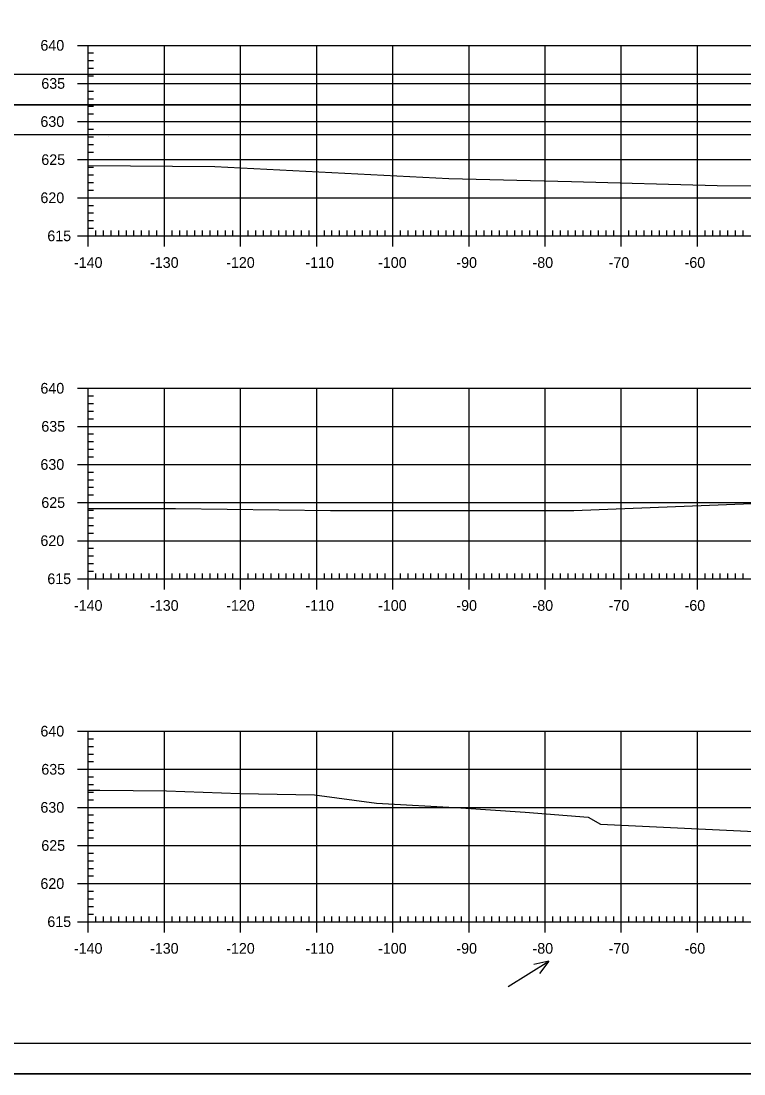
# Model space of a CAD drawing. Extents: x 1381471 to 1382703, y 370300 to 371487.
# Drawn here: x 1381987.8 to 1382082.7, y 370633.8 to 370772 of the extents above; entities that cross this region are included whole.
import ezdxf

# ---------------------------------------------------------------- set-up
doc = ezdxf.new("R2010")
doc.units = 0
for name, color, linetype in [('Level 26', 7, 'Continuous'), ('Level 40', 7, 'Continuous'), ('Level 45', 7, 'Continuous'), ('Level 6', 7, 'Continuous')]:
    doc.layers.add(name, color=color, linetype=linetype)

msp = doc.modelspace()

# ---------------------------------------------------------------- linework, layer by layer
at = {"layer": 'Level 26'}
msp.add_line((1381834.37, 370760.97), (1382167.7, 370760.97), dxfattribs=at)
msp.add_line((1381834.37, 370760.97), (1382167.7, 370760.97), dxfattribs=at)
for points in [[(1381834.36, 370974.3), (1382167.7, 370974.3), (1382167.7, 370760.97), (1381834.36, 370760.97)], [(1382080.69, 370970.41), (1382100.31, 370970.41), (1382100.31, 370960.53), (1382116.42, 370960.53), (1382139.62, 370960.53), (1382139.62, 370927.86), (1382162.83, 370927.86), (1382162.95, 370764.95), (1381846.77, 370764.95), (1381846.77, 370970.41)], [(1381834.36, 370760.97), (1382167.7, 370760.97), (1382167.7, 370547.63), (1381834.36, 370547.63)], [(1382080.69, 370757.07), (1382100.31, 370757.07), (1382100.31, 370747.19), (1382116.42, 370747.19), (1382139.62, 370747.19), (1382139.62, 370714.52), (1382162.83, 370714.52), (1382162.95, 370551.61), (1381846.77, 370551.61), (1381846.77, 370757.07)]]:
    msp.add_lwpolyline(points, close=True, dxfattribs=at)
at = {"layer": 'Level 40'}
for p, q in [((1382051.77, 370645.28), (1382057.11, 370648.58)), ((1382057.11, 370648.58), (1382055.11, 370648.16)), ((1382057.11, 370648.58), (1382055.85, 370646.97))]:
    msp.add_line(p, q, dxfattribs=at)
at = {"layer": 'Level 45'}
for p, q in [((1381995.21, 370768.78), (1381998.01, 370768.78)), ((1381996.61, 370768.78), (1382276.61, 370768.78)), ((1381996.61, 370743.78), (1381996.61, 370768.78)), ((1381996.61, 370743.78), (1381996.61, 370768.78)), ((1382006.61, 370743.78), (1382006.61, 370768.78)), ((1382016.61, 370743.78), (1382016.61, 370768.78)), ((1382026.61, 370743.78), (1382026.61, 370768.78)), ((1382036.61, 370743.78), (1382036.61, 370768.78)), ((1382046.61, 370743.78), (1382046.61, 370768.78)), ((1382056.61, 370743.78), (1382056.61, 370768.78)), ((1382066.61, 370743.78), (1382066.61, 370768.78)), ((1382076.61, 370743.78), (1382076.61, 370768.78)), ((1381996.61, 370767.78), (1381997.31, 370767.78)), ((1381996.61, 370766.78), (1381997.31, 370766.78)), ((1381996.61, 370765.78), (1381997.31, 370765.78)), ((1381996.61, 370764.78), (1381997.31, 370764.78)), ((1381995.21, 370763.78), (1381998.01, 370763.78)), ((1381996.61, 370763.78), (1382276.61, 370763.78)), ((1381996.61, 370762.78), (1381997.31, 370762.78)), ((1381996.61, 370761.78), (1381997.31, 370761.78)), ((1381996.61, 370760.78), (1381997.31, 370760.78)), ((1381995.21, 370758.78), (1381998.01, 370758.78)), ((1381996.61, 370759.78), (1381997.31, 370759.78)), ((1381996.61, 370758.78), (1382276.61, 370758.78)), ((1381996.61, 370757.78), (1381997.31, 370757.78)), ((1381996.61, 370756.78), (1381997.31, 370756.78)), ((1381996.61, 370755.78), (1381997.31, 370755.78)), ((1381996.61, 370754.78), (1381997.31, 370754.78)), ((1381995.21, 370753.78), (1381998.01, 370753.78)), ((1381996.61, 370753.78), (1382276.61, 370753.78)), ((1381996.61, 370752.78), (1381997.31, 370752.78)), ((1381996.61, 370751.78), (1381997.31, 370751.78)), ((1381996.61, 370750.78), (1381997.31, 370750.78)), ((1381995.21, 370748.78), (1381998.01, 370748.78)), ((1381996.61, 370749.78), (1381997.31, 370749.78)), ((1381996.61, 370748.78), (1382276.61, 370748.78)), ((1381996.61, 370747.78), (1381997.31, 370747.78)), ((1381996.61, 370746.78), (1381997.31, 370746.78)), ((1381996.61, 370745.78), (1381997.31, 370745.78)), ((1381996.61, 370742.38), (1381996.61, 370745.18)), ((1381996.61, 370744.78), (1381997.31, 370744.78)), ((1382006.61, 370742.38), (1382006.61, 370745.18)), ((1382016.61, 370742.38), (1382016.61, 370745.18)), ((1382026.61, 370742.38), (1382026.61, 370745.18)), ((1382036.61, 370742.38), (1382036.61, 370745.18)), ((1382046.61, 370742.38), (1382046.61, 370745.18)), ((1382056.61, 370742.38), (1382056.61, 370745.18)), ((1382066.61, 370742.38), (1382066.61, 370745.18)), ((1382076.61, 370742.38), (1382076.61, 370745.18)), ((1381995.21, 370743.78), (1381998.01, 370743.78)), ((1381996.61, 370743.78), (1382276.61, 370743.78)), ((1381996.61, 370743.78), (1382276.61, 370743.78)), ((1381997.61, 370743.78), (1381997.61, 370744.48)), ((1381998.61, 370743.78), (1381998.61, 370744.48)), ((1381999.61, 370743.78), (1381999.61, 370744.48)), ((1382000.61, 370743.78), (1382000.61, 370744.48)), ((1382001.61, 370743.78), (1382001.61, 370744.48)), ((1382002.61, 370743.78), (1382002.61, 370744.48)), ((1382003.61, 370743.78), (1382003.61, 370744.48)), ((1382004.61, 370743.78), (1382004.61, 370744.48)), ((1382005.61, 370743.78), (1382005.61, 370744.48)), ((1382007.61, 370743.78), (1382007.61, 370744.48)), ((1382008.61, 370743.78), (1382008.61, 370744.48)), ((1382009.61, 370743.78), (1382009.61, 370744.48)), ((1382010.61, 370743.78), (1382010.61, 370744.48)), ((1382011.61, 370743.78), (1382011.61, 370744.48)), ((1382012.61, 370743.78), (1382012.61, 370744.48)), ((1382013.61, 370743.78), (1382013.61, 370744.48)), ((1382014.61, 370743.78), (1382014.61, 370744.48)), ((1382015.61, 370743.78), (1382015.61, 370744.48)), ((1382017.61, 370743.78), (1382017.61, 370744.48)), ((1382018.61, 370743.78), (1382018.61, 370744.48)), ((1382019.61, 370743.78), (1382019.61, 370744.48)), ((1382020.61, 370743.78), (1382020.61, 370744.48)), ((1382021.61, 370743.78), (1382021.61, 370744.48)), ((1382022.61, 370743.78), (1382022.61, 370744.48)), ((1382023.61, 370743.78), (1382023.61, 370744.48)), ((1382024.61, 370743.78), (1382024.61, 370744.48)), ((1382025.61, 370743.78), (1382025.61, 370744.48)), ((1382027.61, 370743.78), (1382027.61, 370744.48)), ((1382028.61, 370743.78), (1382028.61, 370744.48)), ((1382029.61, 370743.78), (1382029.61, 370744.48)), ((1382030.61, 370743.78), (1382030.61, 370744.48)), ((1382031.61, 370743.78), (1382031.61, 370744.48)), ((1382032.61, 370743.78), (1382032.61, 370744.48)), ((1382033.61, 370743.78), (1382033.61, 370744.48)), ((1382034.61, 370743.78), (1382034.61, 370744.48)), ((1382035.61, 370743.78), (1382035.61, 370744.48)), ((1382037.61, 370743.78), (1382037.61, 370744.48)), ((1382038.61, 370743.78), (1382038.61, 370744.48)), ((1382039.61, 370743.78), (1382039.61, 370744.48)), ((1382040.61, 370743.78), (1382040.61, 370744.48)), ((1382041.61, 370743.78), (1382041.61, 370744.48)), ((1382042.61, 370743.78), (1382042.61, 370744.48)), ((1382043.61, 370743.78), (1382043.61, 370744.48)), ((1382044.61, 370743.78), (1382044.61, 370744.48)), ((1382045.61, 370743.78), (1382045.61, 370744.48)), ((1382047.61, 370743.78), (1382047.61, 370744.48)), ((1382048.61, 370743.78), (1382048.61, 370744.48)), ((1382049.61, 370743.78), (1382049.61, 370744.48)), ((1382050.61, 370743.78), (1382050.61, 370744.48)), ((1382051.61, 370743.78), (1382051.61, 370744.48)), ((1382052.61, 370743.78), (1382052.61, 370744.48)), ((1382053.61, 370743.78), (1382053.61, 370744.48)), ((1382054.61, 370743.78), (1382054.61, 370744.48)), ((1382055.61, 370743.78), (1382055.61, 370744.48)), ((1382057.61, 370743.78), (1382057.61, 370744.48)), ((1382058.61, 370743.78), (1382058.61, 370744.48)), ((1382059.61, 370743.78), (1382059.61, 370744.48)), ((1382060.61, 370743.78), (1382060.61, 370744.48)), ((1382061.61, 370743.78), (1382061.61, 370744.48)), ((1382062.61, 370743.78), (1382062.61, 370744.48)), ((1382063.61, 370743.78), (1382063.61, 370744.48)), ((1382064.61, 370743.78), (1382064.61, 370744.48)), ((1382065.61, 370743.78), (1382065.61, 370744.48)), ((1382067.61, 370743.78), (1382067.61, 370744.48)), ((1382068.61, 370743.78), (1382068.61, 370744.48)), ((1382069.61, 370743.78), (1382069.61, 370744.48)), ((1382070.61, 370743.78), (1382070.61, 370744.48)), ((1382071.61, 370743.78), (1382071.61, 370744.48)), ((1382072.61, 370743.78), (1382072.61, 370744.48)), ((1382073.61, 370743.78), (1382073.61, 370744.48)), ((1382074.61, 370743.78), (1382074.61, 370744.48)), ((1382075.61, 370743.78), (1382075.61, 370744.48)), ((1382077.61, 370743.78), (1382077.61, 370744.48)), ((1382078.61, 370743.78), (1382078.61, 370744.48)), ((1382079.61, 370743.78), (1382079.61, 370744.48)), ((1382080.61, 370743.78), (1382080.61, 370744.48)), ((1382081.61, 370743.78), (1382081.61, 370744.48)), ((1382082.61, 370743.78), (1382082.61, 370744.48)), ((1381995.21, 370723.78), (1381998.01, 370723.78)), ((1381996.61, 370723.78), (1382276.61, 370723.78)), ((1381996.61, 370698.78), (1381996.61, 370723.78)), ((1381996.61, 370698.78), (1381996.61, 370723.78)), ((1381996.61, 370722.78), (1381997.31, 370722.78)), ((1382006.61, 370698.78), (1382006.61, 370723.78)), ((1382016.61, 370698.78), (1382016.61, 370723.78)), ((1382026.61, 370698.78), (1382026.61, 370723.78)), ((1382036.61, 370698.78), (1382036.61, 370723.78)), ((1382046.61, 370698.78), (1382046.61, 370723.78)), ((1382056.61, 370698.78), (1382056.61, 370723.78)), ((1382066.61, 370698.78), (1382066.61, 370723.78)), ((1382076.61, 370698.78), (1382076.61, 370723.78)), ((1381996.61, 370721.78), (1381997.31, 370721.78)), ((1381996.61, 370720.78), (1381997.31, 370720.78)), ((1381996.61, 370719.78), (1381997.31, 370719.78)), ((1381995.21, 370718.78), (1381998.01, 370718.78)), ((1381996.61, 370718.78), (1382276.61, 370718.78)), ((1381996.61, 370717.78), (1381997.31, 370717.78)), ((1381996.61, 370716.78), (1381997.31, 370716.78)), ((1381996.61, 370715.78), (1381997.31, 370715.78)), ((1381996.61, 370714.78), (1381997.31, 370714.78)), ((1381995.21, 370713.78), (1381998.01, 370713.78)), ((1381996.61, 370713.78), (1382276.61, 370713.78)), ((1381996.61, 370712.78), (1381997.31, 370712.78)), ((1381996.61, 370711.78), (1381997.31, 370711.78)), ((1381996.61, 370710.78), (1381997.31, 370710.78)), ((1381995.21, 370708.78), (1381998.01, 370708.78)), ((1381996.61, 370709.78), (1381997.31, 370709.78)), ((1381996.61, 370708.78), (1382276.61, 370708.78)), ((1381996.61, 370707.78), (1381997.31, 370707.78)), ((1381996.61, 370706.78), (1381997.31, 370706.78)), ((1381996.61, 370705.78), (1381997.31, 370705.78)), ((1381996.61, 370704.78), (1381997.31, 370704.78)), ((1381995.21, 370703.78), (1381998.01, 370703.78)), ((1381996.61, 370703.78), (1382276.61, 370703.78)), ((1381996.61, 370702.78), (1381997.31, 370702.78)), ((1381996.61, 370701.78), (1381997.31, 370701.78)), ((1381996.61, 370700.78), (1381997.31, 370700.78)), ((1381996.61, 370697.38), (1381996.61, 370700.18)), ((1381996.61, 370699.78), (1381997.31, 370699.78)), ((1381997.61, 370698.78), (1381997.61, 370699.48)), ((1381998.61, 370698.78), (1381998.61, 370699.48)), ((1381999.61, 370698.78), (1381999.61, 370699.48)), ((1382000.61, 370698.78), (1382000.61, 370699.48)), ((1382001.61, 370698.78), (1382001.61, 370699.48)), ((1382002.61, 370698.78), (1382002.61, 370699.48)), ((1382003.61, 370698.78), (1382003.61, 370699.48)), ((1382004.61, 370698.78), (1382004.61, 370699.48)), ((1382005.61, 370698.78), (1382005.61, 370699.48)), ((1382006.61, 370697.38), (1382006.61, 370700.18)), ((1382007.61, 370698.78), (1382007.61, 370699.48)), ((1382008.61, 370698.78), (1382008.61, 370699.48)), ((1382009.61, 370698.78), (1382009.61, 370699.48)), ((1382010.61, 370698.78), (1382010.61, 370699.48)), ((1382011.61, 370698.78), (1382011.61, 370699.48)), ((1382012.61, 370698.78), (1382012.61, 370699.48)), ((1382013.61, 370698.78), (1382013.61, 370699.48)), ((1382014.61, 370698.78), (1382014.61, 370699.48)), ((1382015.61, 370698.78), (1382015.61, 370699.48)), ((1382016.61, 370697.38), (1382016.61, 370700.18)), ((1382017.61, 370698.78), (1382017.61, 370699.48)), ((1382018.61, 370698.78), (1382018.61, 370699.48)), ((1382019.61, 370698.78), (1382019.61, 370699.48)), ((1382020.61, 370698.78), (1382020.61, 370699.48)), ((1382021.61, 370698.78), (1382021.61, 370699.48)), ((1382022.61, 370698.78), (1382022.61, 370699.48)), ((1382023.61, 370698.78), (1382023.61, 370699.48)), ((1382024.61, 370698.78), (1382024.61, 370699.48)), ((1382025.61, 370698.78), (1382025.61, 370699.48)), ((1382026.61, 370697.38), (1382026.61, 370700.18)), ((1382027.61, 370698.78), (1382027.61, 370699.48)), ((1382028.61, 370698.78), (1382028.61, 370699.48)), ((1382029.61, 370698.78), (1382029.61, 370699.48)), ((1382030.61, 370698.78), (1382030.61, 370699.48)), ((1382031.61, 370698.78), (1382031.61, 370699.48)), ((1382032.61, 370698.78), (1382032.61, 370699.48)), ((1382033.61, 370698.78), (1382033.61, 370699.48)), ((1382034.61, 370698.78), (1382034.61, 370699.48)), ((1382035.61, 370698.78), (1382035.61, 370699.48)), ((1382036.61, 370697.38), (1382036.61, 370700.18)), ((1382037.61, 370698.78), (1382037.61, 370699.48)), ((1382038.61, 370698.78), (1382038.61, 370699.48)), ((1382039.61, 370698.78), (1382039.61, 370699.48)), ((1382040.61, 370698.78), (1382040.61, 370699.48)), ((1382041.61, 370698.78), (1382041.61, 370699.48)), ((1382042.61, 370698.78), (1382042.61, 370699.48)), ((1382043.61, 370698.78), (1382043.61, 370699.48)), ((1382044.61, 370698.78), (1382044.61, 370699.48)), ((1382045.61, 370698.78), (1382045.61, 370699.48)), ((1382046.61, 370697.38), (1382046.61, 370700.18)), ((1382047.61, 370698.78), (1382047.61, 370699.48)), ((1382048.61, 370698.78), (1382048.61, 370699.48)), ((1382049.61, 370698.78), (1382049.61, 370699.48)), ((1382050.61, 370698.78), (1382050.61, 370699.48)), ((1382051.61, 370698.78), (1382051.61, 370699.48)), ((1382052.61, 370698.78), (1382052.61, 370699.48)), ((1382053.61, 370698.78), (1382053.61, 370699.48)), ((1382054.61, 370698.78), (1382054.61, 370699.48)), ((1382055.61, 370698.78), (1382055.61, 370699.48)), ((1382056.61, 370697.38), (1382056.61, 370700.18)), ((1382057.61, 370698.78), (1382057.61, 370699.48)), ((1382058.61, 370698.78), (1382058.61, 370699.48)), ((1382059.61, 370698.78), (1382059.61, 370699.48)), ((1382060.61, 370698.78), (1382060.61, 370699.48)), ((1382061.61, 370698.78), (1382061.61, 370699.48)), ((1382062.61, 370698.78), (1382062.61, 370699.48)), ((1382063.61, 370698.78), (1382063.61, 370699.48)), ((1382064.61, 370698.78), (1382064.61, 370699.48)), ((1382065.61, 370698.78), (1382065.61, 370699.48)), ((1382066.61, 370697.38), (1382066.61, 370700.18)), ((1382067.61, 370698.78), (1382067.61, 370699.48)), ((1382068.61, 370698.78), (1382068.61, 370699.48)), ((1382069.61, 370698.78), (1382069.61, 370699.48)), ((1382070.61, 370698.78), (1382070.61, 370699.48)), ((1382071.61, 370698.78), (1382071.61, 370699.48)), ((1382072.61, 370698.78), (1382072.61, 370699.48)), ((1382073.61, 370698.78), (1382073.61, 370699.48)), ((1382074.61, 370698.78), (1382074.61, 370699.48)), ((1382075.61, 370698.78), (1382075.61, 370699.48)), ((1382076.61, 370697.38), (1382076.61, 370700.18)), ((1382077.61, 370698.78), (1382077.61, 370699.48)), ((1382078.61, 370698.78), (1382078.61, 370699.48)), ((1382079.61, 370698.78), (1382079.61, 370699.48)), ((1382080.61, 370698.78), (1382080.61, 370699.48)), ((1382081.61, 370698.78), (1382081.61, 370699.48)), ((1382082.61, 370698.78), (1382082.61, 370699.48)), ((1381995.21, 370698.78), (1381998.01, 370698.78)), ((1381996.61, 370698.78), (1382276.61, 370698.78)), ((1381996.61, 370698.78), (1382276.61, 370698.78)), ((1381995.21, 370678.78), (1381998.01, 370678.78)), ((1381996.61, 370678.78), (1382276.61, 370678.78)), ((1381996.61, 370653.78), (1381996.61, 370678.78)), ((1381996.61, 370653.78), (1381996.61, 370678.78)), ((1382006.61, 370653.78), (1382006.61, 370678.78)), ((1382016.61, 370653.78), (1382016.61, 370678.78)), ((1382026.61, 370653.78), (1382026.61, 370678.78)), ((1382036.61, 370653.78), (1382036.61, 370678.78)), ((1382046.61, 370653.78), (1382046.61, 370678.78)), ((1382056.61, 370653.78), (1382056.61, 370678.78)), ((1382066.61, 370653.78), (1382066.61, 370678.78)), ((1382076.61, 370653.78), (1382076.61, 370678.78)), ((1381996.61, 370677.78), (1381997.31, 370677.78)), ((1381996.61, 370676.78), (1381997.31, 370676.78)), ((1381996.61, 370675.78), (1381997.31, 370675.78)), ((1381996.61, 370674.78), (1381997.31, 370674.78)), ((1381995.21, 370673.78), (1381998.01, 370673.78)), ((1381996.61, 370673.78), (1382276.61, 370673.78)), ((1381996.61, 370672.78), (1381997.31, 370672.78)), ((1381996.61, 370671.78), (1381997.31, 370671.78)), ((1381996.61, 370670.78), (1381997.31, 370670.78)), ((1381995.21, 370668.78), (1381998.01, 370668.78)), ((1381996.61, 370669.78), (1381997.31, 370669.78)), ((1381996.61, 370668.78), (1382276.61, 370668.78)), ((1381996.61, 370667.78), (1381997.31, 370667.78)), ((1381996.61, 370666.78), (1381997.31, 370666.78)), ((1381996.61, 370665.78), (1381997.31, 370665.78)), ((1381996.61, 370664.78), (1381997.31, 370664.78)), ((1381995.21, 370663.78), (1381998.01, 370663.78)), ((1381996.61, 370663.78), (1382276.61, 370663.78)), ((1381996.61, 370662.78), (1381997.31, 370662.78)), ((1381996.61, 370661.78), (1381997.31, 370661.78)), ((1381996.61, 370660.78), (1381997.31, 370660.78)), ((1381996.61, 370659.78), (1381997.31, 370659.78)), ((1381995.21, 370658.78), (1381998.01, 370658.78)), ((1381996.61, 370658.78), (1382276.61, 370658.78)), ((1381996.61, 370657.78), (1381997.31, 370657.78)), ((1381996.61, 370656.78), (1381997.31, 370656.78)), ((1381996.61, 370655.78), (1381997.31, 370655.78)), ((1381996.61, 370652.38), (1381996.61, 370655.18)), ((1382006.61, 370652.38), (1382006.61, 370655.18)), ((1382016.61, 370652.38), (1382016.61, 370655.18)), ((1382026.61, 370652.38), (1382026.61, 370655.18)), ((1382036.61, 370652.38), (1382036.61, 370655.18)), ((1382046.61, 370652.38), (1382046.61, 370655.18)), ((1382056.61, 370652.38), (1382056.61, 370655.18)), ((1382066.61, 370652.38), (1382066.61, 370655.18)), ((1382076.61, 370652.38), (1382076.61, 370655.18)), ((1381995.21, 370653.78), (1381998.01, 370653.78)), ((1381996.61, 370654.78), (1381997.31, 370654.78)), ((1381996.61, 370653.78), (1382276.61, 370653.78)), ((1381996.61, 370653.78), (1382276.61, 370653.78)), ((1381997.61, 370653.78), (1381997.61, 370654.48)), ((1381998.61, 370653.78), (1381998.61, 370654.48)), ((1381999.61, 370653.78), (1381999.61, 370654.48)), ((1382000.61, 370653.78), (1382000.61, 370654.48)), ((1382001.61, 370653.78), (1382001.61, 370654.48)), ((1382002.61, 370653.78), (1382002.61, 370654.48)), ((1382003.61, 370653.78), (1382003.61, 370654.48)), ((1382004.61, 370653.78), (1382004.61, 370654.48)), ((1382005.61, 370653.78), (1382005.61, 370654.48)), ((1382007.61, 370653.78), (1382007.61, 370654.48)), ((1382008.61, 370653.78), (1382008.61, 370654.48)), ((1382009.61, 370653.78), (1382009.61, 370654.48)), ((1382010.61, 370653.78), (1382010.61, 370654.48)), ((1382011.61, 370653.78), (1382011.61, 370654.48)), ((1382012.61, 370653.78), (1382012.61, 370654.48)), ((1382013.61, 370653.78), (1382013.61, 370654.48)), ((1382014.61, 370653.78), (1382014.61, 370654.48)), ((1382015.61, 370653.78), (1382015.61, 370654.48)), ((1382017.61, 370653.78), (1382017.61, 370654.48)), ((1382018.61, 370653.78), (1382018.61, 370654.48)), ((1382019.61, 370653.78), (1382019.61, 370654.48)), ((1382020.61, 370653.78), (1382020.61, 370654.48)), ((1382021.61, 370653.78), (1382021.61, 370654.48)), ((1382022.61, 370653.78), (1382022.61, 370654.48)), ((1382023.61, 370653.78), (1382023.61, 370654.48)), ((1382024.61, 370653.78), (1382024.61, 370654.48)), ((1382025.61, 370653.78), (1382025.61, 370654.48)), ((1382027.61, 370653.78), (1382027.61, 370654.48)), ((1382028.61, 370653.78), (1382028.61, 370654.48)), ((1382029.61, 370653.78), (1382029.61, 370654.48)), ((1382030.61, 370653.78), (1382030.61, 370654.48)), ((1382031.61, 370653.78), (1382031.61, 370654.48)), ((1382032.61, 370653.78), (1382032.61, 370654.48)), ((1382033.61, 370653.78), (1382033.61, 370654.48)), ((1382034.61, 370653.78), (1382034.61, 370654.48)), ((1382035.61, 370653.78), (1382035.61, 370654.48)), ((1382037.61, 370653.78), (1382037.61, 370654.48)), ((1382038.61, 370653.78), (1382038.61, 370654.48)), ((1382039.61, 370653.78), (1382039.61, 370654.48)), ((1382040.61, 370653.78), (1382040.61, 370654.48)), ((1382041.61, 370653.78), (1382041.61, 370654.48)), ((1382042.61, 370653.78), (1382042.61, 370654.48)), ((1382043.61, 370653.78), (1382043.61, 370654.48)), ((1382044.61, 370653.78), (1382044.61, 370654.48)), ((1382045.61, 370653.78), (1382045.61, 370654.48)), ((1382047.61, 370653.78), (1382047.61, 370654.48)), ((1382048.61, 370653.78), (1382048.61, 370654.48)), ((1382049.61, 370653.78), (1382049.61, 370654.48)), ((1382050.61, 370653.78), (1382050.61, 370654.48)), ((1382051.61, 370653.78), (1382051.61, 370654.48)), ((1382052.61, 370653.78), (1382052.61, 370654.48)), ((1382053.61, 370653.78), (1382053.61, 370654.48)), ((1382054.61, 370653.78), (1382054.61, 370654.48)), ((1382055.61, 370653.78), (1382055.61, 370654.48)), ((1382057.61, 370653.78), (1382057.61, 370654.48)), ((1382058.61, 370653.78), (1382058.61, 370654.48)), ((1382059.61, 370653.78), (1382059.61, 370654.48)), ((1382060.61, 370653.78), (1382060.61, 370654.48)), ((1382061.61, 370653.78), (1382061.61, 370654.48)), ((1382062.61, 370653.78), (1382062.61, 370654.48)), ((1382063.61, 370653.78), (1382063.61, 370654.48)), ((1382064.61, 370653.78), (1382064.61, 370654.48)), ((1382065.61, 370653.78), (1382065.61, 370654.48)), ((1382067.61, 370653.78), (1382067.61, 370654.48)), ((1382068.61, 370653.78), (1382068.61, 370654.48)), ((1382069.61, 370653.78), (1382069.61, 370654.48)), ((1382070.61, 370653.78), (1382070.61, 370654.48)), ((1382071.61, 370653.78), (1382071.61, 370654.48)), ((1382072.61, 370653.78), (1382072.61, 370654.48)), ((1382073.61, 370653.78), (1382073.61, 370654.48)), ((1382074.61, 370653.78), (1382074.61, 370654.48)), ((1382075.61, 370653.78), (1382075.61, 370654.48)), ((1382077.61, 370653.78), (1382077.61, 370654.48)), ((1382078.61, 370653.78), (1382078.61, 370654.48)), ((1382079.61, 370653.78), (1382079.61, 370654.48)), ((1382080.61, 370653.78), (1382080.61, 370654.48)), ((1382081.61, 370653.78), (1382081.61, 370654.48)), ((1382082.61, 370653.78), (1382082.61, 370654.48)), ((1382294.79, 370637.78), (1381978.61, 370637.78)), ((1381966.21, 370633.8), (1382299.55, 370633.8))]:
    msp.add_line(p, q, dxfattribs=at)
for points in [[(1381966.21, 370847.14), (1382299.55, 370847.14), (1382299.55, 370633.8), (1381966.21, 370633.8)], [(1382212.53, 370843.24), (1382232.15, 370843.24), (1382232.15, 370833.36), (1382248.27, 370833.36), (1382271.46, 370833.36), (1382271.46, 370809.03), (1382294.79, 370809.03), (1382294.79, 370637.78), (1381978.61, 370637.78), (1381978.61, 370843.24)]]:
    msp.add_lwpolyline(points, close=True, dxfattribs=at)
for points in [[(1381996.61, 370753.02), (1382013.21, 370752.87), (1382043.96, 370751.3), (1382060.08, 370750.92), (1382079.19, 370750.37), (1382120.54, 370750.21), (1382124.19, 370751.07), (1382125.2, 370751.35), (1382144.86, 370749.4), (1382146.07, 370749.24), (1382146.55, 370749.13), (1382150, 370748.83), (1382154.14, 370749.71), (1382161.7, 370750.29), (1382170.64, 370750.82), (1382184.54, 370750.7)], [(1381996.61, 370707.98), (1382008.04, 370707.99), (1382028.41, 370707.75), (1382060.37, 370707.75), (1382100.47, 370709.33)], [(1381996.61, 370671.06), (1381998.13, 370671.04), (1382006.86, 370670.93), (1382016.52, 370670.62), (1382026.33, 370670.41), (1382034.45, 370669.35), (1382045.53, 370668.74), (1382053.99, 370668.13), (1382062.28, 370667.48), (1382063.87, 370666.56), (1382092.39, 370665.24)]]:
    msp.add_lwpolyline(points, dxfattribs=at)
at = {"layer": 'Level 6'}
for p, q in [((1382162.95, 370764.95), (1381846.77, 370764.95)), ((1381846.77, 370757.07), (1382162.95, 370757.07)), ((1381999.29, 370756.81), (1381999.29, 370756.81)), ((1381999.29, 370756.81), (1381999.29, 370756.81))]:
    msp.add_line(p, q, dxfattribs=at)

# ---------------------------------------------------------------- texts
at = {"layer": 'Level 45'}
for s, p in [('640', (1381990.32, 370768.08)), ('635', (1381990.44, 370763.08)), ('630', (1381990.32, 370758.08)), ('625', (1381990.44, 370753.08)), ('620', (1381990.32, 370748.08)), ('615', (1381991.23, 370743.08)), ('-140', (1381994.72, 370739.58)), ('-130', (1382004.72, 370739.58)), ('-120', (1382014.72, 370739.58)), ('-110', (1382025.12, 370739.58)), ('-100', (1382034.67, 370739.58)), ('-90', (1382044.95, 370739.58)), ('-80', (1382054.95, 370739.58)), ('-70', (1382064.95, 370739.58)), ('-60', (1382074.92, 370739.58)), ('640', (1381990.32, 370723.08)), ('635', (1381990.44, 370718.08)), ('630', (1381990.32, 370713.08)), ('625', (1381990.44, 370708.08)), ('620', (1381990.32, 370703.08)), ('615', (1381991.23, 370698.08)), ('-140', (1381994.72, 370694.58)), ('-130', (1382004.72, 370694.58)), ('-120', (1382014.72, 370694.58)), ('-110', (1382025.12, 370694.58)), ('-100', (1382034.67, 370694.58)), ('-90', (1382044.95, 370694.58)), ('-80', (1382054.95, 370694.58)), ('-70', (1382064.95, 370694.58)), ('-60', (1382074.92, 370694.58)), ('640', (1381990.32, 370678.08)), ('635', (1381990.44, 370673.08)), ('630', (1381990.32, 370668.08)), ('625', (1381990.44, 370663.08)), ('620', (1381990.32, 370658.08)), ('615', (1381991.23, 370653.08)), ('-140', (1381994.72, 370649.58)), ('-130', (1382004.72, 370649.58)), ('-120', (1382014.72, 370649.58)), ('-110', (1382025.12, 370649.58)), ('-100', (1382034.67, 370649.58)), ('-90', (1382044.95, 370649.58)), ('-80', (1382054.95, 370649.58)), ('-70', (1382064.95, 370649.58)), ('-60', (1382074.92, 370649.58))]:
    msp.add_text(s, height=1.4, dxfattribs=at).set_placement(p)

doc.saveas('drawing.dxf')
